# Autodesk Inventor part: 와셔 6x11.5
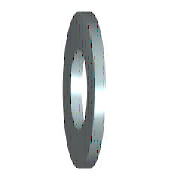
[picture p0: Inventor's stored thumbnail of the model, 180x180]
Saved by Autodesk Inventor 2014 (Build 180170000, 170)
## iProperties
IsCustomPart: 1
Created: 2012-02
Part Number: 와셔 6x11.5
Material: 강철, 연강
Description: 평면 와셔
Document SubType Name: Modeling
Standard: KS B 1326
Designer: mduedu
Standards Organization: KS
Language: ko-KR
Size Designation: 6x11.5
Categories: <MemberInstance><Categories><Category DisplayName="조임쇠" InternalName="e4da775c-781d-43d5-af7c-5136215cf5a6" Mnemonic="FSTN"><Category DisplayName="와셔" InternalN
Density: 1 g/cm^3
Appearance: 분홍색
Author: mduedu
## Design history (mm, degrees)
sketch "스케치"
  geometry: C1 r 5.75 at (0, 0); C2 r 3.2 at (0, 0); 1 further point
  constraints: 2 centre point, 2 coincident
  dimensions: "d0" = 6.4 diameter of C2 (= SD1); "d1" = 11.5 diameter of C1 (= SD2)
extrude "본체" new body sketch "스케치" distance "d2" = 1.6 (= SD); taper "d3" = 0 deg
workaxis "Work Axis1"
workplane "Work Plane1"
body "Solid1"
other parameters: "SD1" = 6.4 [user parameter; used in 1 equation term], "SD2" = 11.5 [user parameter; used in 1 equation term], "SD" = 1.6 [user parameter; used in 1 equation term], "d4" = 0, "d5" = 0, "d6" = 0, "d7" = 0, "NND" = 6 [user parameter]
